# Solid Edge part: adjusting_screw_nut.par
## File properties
Title: Adjusting screw nut
Author: Abhinav Rai
Template: Normal.par
Last saved by: TIET
Revision: 17
Application: Solid Edge
Accuracy: 0.99
Material: aluminum
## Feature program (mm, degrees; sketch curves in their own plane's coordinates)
sketch for "unnamed RevolvedProtrusion 1" plane through (0, 0, 0) normal (0, -1, 0) x-axis (1, 0, 0)
  line (38.1, 9.7462) -> (74.676, 9.7462)
  line (76.2, 8.2222) -> (74.676, 9.7462)
  line (76.2, -26.8298) -> (76.2, 8.2222)
  line (76.2, -26.8298) -> (74.676, -28.3538)
  line (74.676, -28.3538) -> (47.625, -28.3538)
  line (47.625, -28.3538) -> (47.625, -60.1038)
  line (47.625, -60.1038) -> (38.1, -60.1038)
  line (38.1, -60.1038) -> (38.1, 9.7462)
revolve "unnamed RevolvedProtrusion 1" add full turn 360 deg
sketch for "Hole_1" plane through (76.2, 0, 0) normal (1, 0, 0) x-axis (0, 1, 0)
  hole centre (0, -9.3038) bore radius 9.5123
hole "Hole_1" diameter 19.0246 finite  VBottomAngle = 118 deg
pattern "unnamed Pattern 1" of "Hole_1"
pattern "unnamed Pattern 2"
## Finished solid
Body 1: solid body, 16 faces, 16 edges, 4 vertices.
  Faces by surface: cylinder 7, cone 6, plane 3
  Edges by curve: circle 12, intersection 4
Bounding box of the edges (mm): 152.400 x 152.400 x 69.850, from (-76.2, -76.2, -60.1038) to (76.2, 76.2, 9.7462).
Cylindrical faces by radius (mm): R9.5123 x4, R38.1 x1, R47.625 x1, R76.2 x1
Conical faces (half-angle, radius in mm at the cone's reference point): 45 deg R74.676 x1, 45 deg R76.2 x1, 59 deg R9.5123 x4
Planar faces by outward normal: +z 1, -z 2
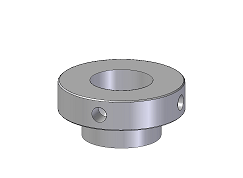
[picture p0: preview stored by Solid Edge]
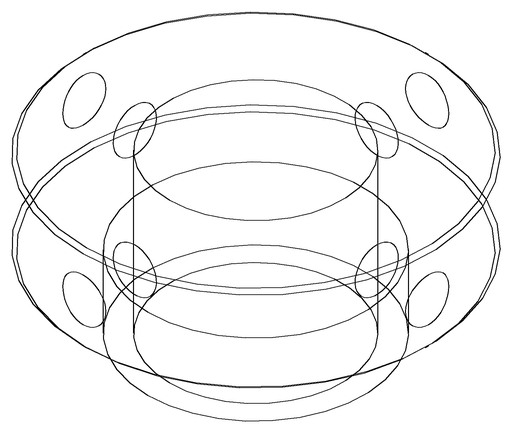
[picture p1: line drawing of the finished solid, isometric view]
